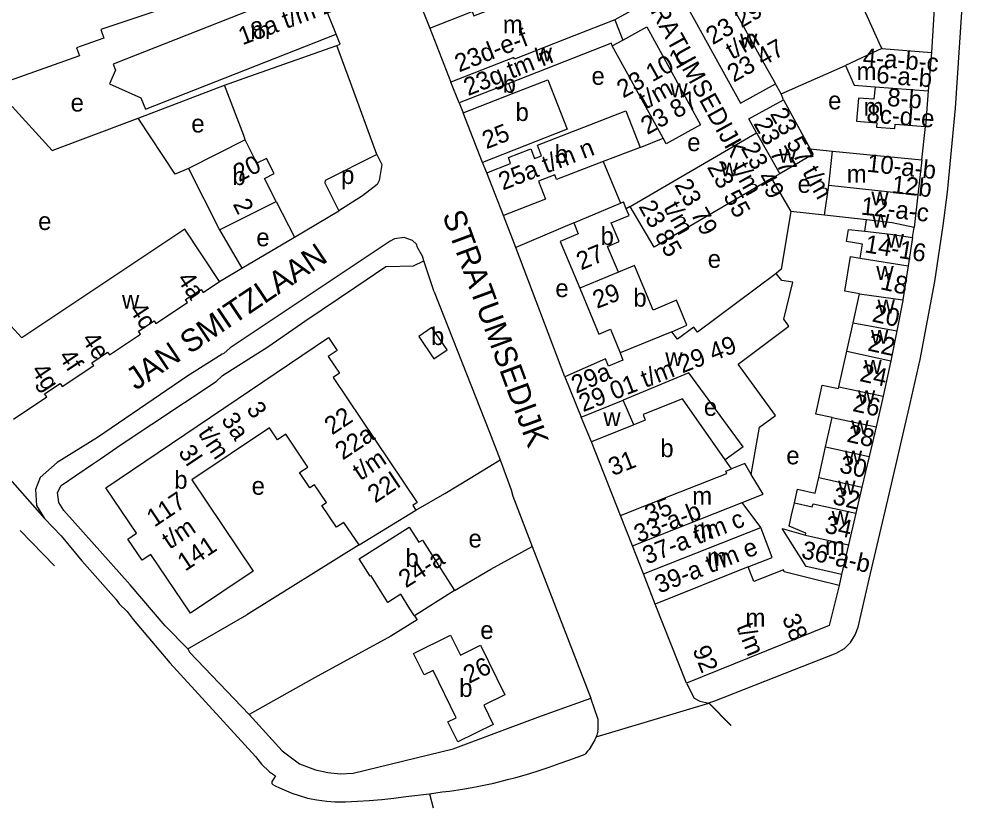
# Model space of a CAD drawing. Extents: x 160673 to 161924, y 382258 to 384145.
# Drawn here: x 161653.4 to 161869.1, y 382580.1 to 382756.1 of the extents above; entities that cross this region are included whole.
import ezdxf

# ---------------------------------------------------------------- set-up
doc = ezdxf.new("R2010")
doc.units = 0
for name, color, linetype in [('BLT_Basislijn', 7, 'Continuous'), ('BLT_Bebouwing', 7, 'Continuous'), ('BLT_Centroide', 7, 'Continuous'), ('BLT_Huisnummer', 7, 'Continuous'), ('BLT_Huisnummer_ tussenligend', 7, 'Continuous'), ('BLT_Huisnummer_reeks', 7, 'Continuous'), ('BLT_Onderdoorgang_en_onderverdeling', 7, 'Continuous'), ('BLT_Onderverdeling_panden', 7, 'Continuous'), ('BLT_Straatnaam', 7, 'Continuous'), ('BLT_Straatnaam_verkleind', 7, 'Continuous'), ('BLT_Vlakafsluiter', 7, 'Continuous')]:
    doc.layers.add(name, color=color, linetype=linetype)

msp = doc.modelspace()

# ---------------------------------------------------------------- linework, layer by layer
at = {"layer": 'BLT_Basislijn'}
for p, q in [((161858.54, 382773.49), (161856.96, 382748.72)), ((161725, 382750.53), (161724.12, 382752.78)), ((161703.58, 382742.99), (161724.28, 382750.28)), ((161724.28, 382750.28), (161725, 382750.53)), ((161727.3, 382742.02), (161724.28, 382750.28)), ((161679.92, 382734.05), (161699.17, 382741.44)), ((161699.17, 382741.44), (161703.58, 382742.99)), ((161733.21, 382725.92), (161727.3, 382742.02)), ((161823.94, 382738.13), (161823.46, 382739.44)), ((161651.83, 382736.65), (161660.76, 382726.8)), ((161660.76, 382726.8), (161678.7, 382733.58)), ((161678.7, 382733.58), (161679.92, 382734.05)), ((161854.84, 382724.77), (161855.64, 382732.18)), ((161791.96, 382727.48), (161797.09, 382729.59)), ((161829.95, 382727.23), (161834.91, 382726.68)), ((161757.72, 382721.84), (161756.79, 382724.17)), ((161783.73, 382724.36), (161787.6, 382715.06)), ((161821.32, 382720.58), (161825.63, 382713.21)), ((161710.71, 382715.47), (161714.79, 382707.51)), ((161714.79, 382707.51), (161724.69, 382713.39)), ((161789.75, 382714.35), (161788.88, 382713.84)), ((161764.23, 382705.15), (161761.43, 382712.3)), ((161698.11, 382709.1), (161703.05, 382700.53)), ((161777.14, 382710.66), (161764.23, 382705.15)), ((161703.05, 382700.53), (161714.79, 382707.51)), ((161775.14, 382676.31), (161764.23, 382705.15)), ((161698.1, 382697.59), (161703.05, 382700.53)), ((161746.02, 382695.31), (161743.67, 382702.18)), ((161717.1, 382688.7), (161728.47, 382696.41)), ((161746.02, 382695.31), (161758.32, 382663.94)), ((161758.32, 382663.94), (161760.69, 382657.74)), ((161671.49, 382658.02), (161673.45, 382659.36)), ((161673.45, 382659.36), (161675.93, 382661.02)), ((161669.7, 382656.79), (161671.49, 382658.02)), ((161653.59, 382641.98), (161661.27, 382634.08)), ((161729.23, 382638.83), (161704.19, 382623.18)), ((161767.86, 382638.41), (161780.96, 382604.55)), ((161836.9, 382632.18), (161836.39, 382629.75)), ((161691.03, 382615.55), (161704.19, 382623.18)), ((161807.26, 382603.48), (161807.31, 382603.5))]:
    msp.add_line(p, q, dxfattribs=at)
for points in [[(161807.31, 382603.5), (161808.62, 382604.01), (161826.42, 382610.98), (161835.69, 382614.61), (161837.55, 382615.63), (161838.9, 382616.97), (161839.97, 382618.7), (161840.6, 382620.41), (161843.11, 382631.15), (161847.83, 382651.39), (161852.26, 382670.37), (161854.47, 382680.15), (161857.74, 382697.6), (161859.63, 382710.05), (161860.56, 382717.51), (161862.36, 382736.25), (161864.15, 382763.42), (161868.36, 382827), (161869.09, 382838.2)], [(161705.29, 382765.14), (161671.57, 382753.82), (161672.26, 382751.88), (161666.99, 382750.02), (161666.19, 382749.74), (161666.83, 382747.94), (161647.7, 382741.2)], [(161703.78, 382729.17), (161703.52, 382730.14), (161699.17, 382741.44)], [(161691.18, 382722.8), (161688.16, 382721.53), (161679.92, 382734.05)], [(161733.21, 382725.92), (161721.67, 382720.16), (161721.6, 382719.59), (161724.69, 382713.39)], [(161733.21, 382725.92), (161734.3, 382723.67), (161733.68, 382720.14), (161733.24, 382719.27), (161729.99, 382716.72), (161724.69, 382713.39)], [(161825.63, 382713.21), (161823.46, 382700.35), (161822.36, 382699.4)], [(161833.12, 382712.37), (161825.63, 382713.21)], [(161743.67, 382702.18), (161743.38, 382703.26), (161742.24, 382705.19), (161742.01, 382705.93), (161741.15, 382706.77), (161739.3, 382707.39), (161737.13, 382707.12), (161736.16, 382706.61), (161700.46, 382682.76), (161699.06, 382681.48), (161698.64, 382681.38), (161690.98, 382676.49), (161670.88, 382662.78), (161661.87, 382657.15), (161658.03, 382653.82), (161657.02, 382651.15), (161657.25, 382647.58), (161659, 382644.71)], [(161728.47, 382696.41), (161735.18, 382700.93), (161741.38, 382701.09), (161743.67, 382702.18)], [(161675.93, 382661.02), (161697.3, 382675.26), (161698.74, 382676.57), (161708.83, 382682.99), (161716.41, 382688.23), (161717.1, 382688.7)], [(161754.05, 382653.68), (161760.69, 382657.74)], [(161760.69, 382657.74), (161763.21, 382651.06), (161763.53, 382649.67), (161767.86, 382638.41)], [(161691.03, 382615.55), (161685.98, 382620.75), (161678.15, 382629.86), (161663.31, 382646.46), (161662.19, 382648.22), (161661.95, 382650.45), (161662.77, 382652.08), (161669.7, 382656.79)], [(161741.88, 382646.56), (161748.39, 382650.23), (161754.05, 382653.68)], [(161659, 382644.71), (161662.77, 382640.82), (161667.34, 382635.24), (161675.02, 382626.6), (161675.65, 382625.64), (161677.43, 382623.92), (161678.77, 382622.1), (161686.99, 382612.44), (161706.14, 382591.55), (161707.48, 382589.83), (161709.23, 382588.1), (161710.6, 382587.23)], [(161750.5, 382628.6), (161758.66, 382633.38), (161767.86, 382638.41)], [(161741.6, 382622.95), (161742.16, 382622.08), (161736.33, 382618.38), (161719.27, 382609.14), (161704.67, 382600.95)], [(161691.03, 382615.55), (161691.41, 382614.82), (161704.67, 382600.95)], [(161802.33, 382607.93), (161804.02, 382604.57), (161805.3, 382603.93), (161807.26, 382603.48)], [(161704.67, 382600.95), (161712.03, 382592.82), (161715.93, 382589.95), (161719.53, 382588.6), (161722.24, 382587.96), (161725.02, 382587.72), (161727.89, 382587.8), (161750.24, 382593.3), (161769.1, 382600.36), (161780.96, 382604.55)], [(161782.52, 382597.2), (161782.62, 382597.64), (161782.57, 382599.81), (161780.96, 382604.55)], [(161782.52, 382597.2), (161782.29, 382596.34), (161782.12, 382595.93)], [(161782.12, 382595.93), (161781.86, 382595.3), (161781.32, 382594.41), (161780.59, 382593.13), (161780.23, 382592.71)], [(161744.97, 382583.21), (161747.8, 382583.63), (161749.4, 382583.79), (161752.35, 382584.23), (161754.47, 382584.62), (161756.71, 382585.06), (161759.33, 382585.62), (161762.38, 382586.39), (161764.2, 382586.85), (161766.57, 382587.53), (161768.96, 382588.26), (161771.66, 382589.15), (161774.15, 382590.03), (161776.04, 382590.74), (161777.91, 382591.4), (161779.7, 382592.06)], [(161710.6, 382587.23), (161709.82, 382586.05), (161709.77, 382585.95), (161709.74, 382585.83), (161709.74, 382585.68), (161709.78, 382585.55), (161709.85, 382585.46), (161709.93, 382585.37), (161710, 382585.33), (161710.53, 382585.04), (161711.5, 382584.56), (161713.02, 382583.86), (161714.2, 382583.4), (161715.87, 382582.82), (161717.71, 382582.28), (161719.79, 382581.86), (161722.03, 382581.57), (161723.85, 382581.45), (161726.19, 382581.45), (161728.89, 382581.55), (161731.51, 382581.7), (161734.34, 382581.94), (161737, 382582.26), (161739.68, 382582.61), (161744.97, 382583.21)]]:
    msp.add_lwpolyline(points, dxfattribs=at)
at = {"layer": 'BLT_Bebouwing'}
for p, q in [((161736.91, 382774.75), (161745, 382754.12)), ((161724.12, 382752.78), (161718.38, 382767.32)), ((161745, 382754.12), (161749.73, 382742.11)), ((161845.9, 382749.6), (161856.96, 382748.72)), ((161856.96, 382748.72), (161856.27, 382740.11)), ((161823.46, 382739.44), (161837.83, 382745.8)), ((161751.57, 382737.48), (161749.73, 382742.11)), ((161763.51, 382739.52), (161762.63, 382741.8)), ((161856.27, 382740.11), (161855.64, 382732.18)), ((161751.57, 382737.48), (161752.44, 382735.22)), ((161756.79, 382724.17), (161752.44, 382735.22)), ((161703.78, 382729.17), (161691.18, 382722.8)), ((161834.1, 382719.12), (161834.91, 382726.68)), ((161834.91, 382726.68), (161854.84, 382724.77)), ((161854.84, 382724.77), (161853.97, 382716.94)), ((161691.18, 382722.8), (161698.11, 382709.1)), ((161761.43, 382712.3), (161757.72, 382721.84)), ((161833.12, 382712.37), (161834.1, 382719.12)), ((161698.11, 382709.1), (161710.71, 382715.47)), ((161787.6, 382715.06), (161788.24, 382715.33)), ((161853.97, 382716.94), (161853.13, 382709.66)), ((161777.14, 382710.66), (161787.6, 382715.06)), ((161842.09, 382708.79), (161842.51, 382711.33)), ((161852.78, 382707.4), (161853.13, 382709.66)), ((161852.78, 382707.4), (161851.81, 382701.05)), ((161851.81, 382701.05), (161850.62, 382693.47)), ((161839.48, 382688.36), (161840.92, 382694.84)), ((161838.08, 382682.05), (161839.48, 382688.36)), ((161849.26, 382686.6), (161847.92, 382679.88)), ((161836.3, 382674.06), (161838.08, 382682.05)), ((161847.92, 382679.88), (161846.18, 382671.98)), ((161775.14, 382676.31), (161778.8, 382667.31)), ((161790.52, 382665.6), (161788.21, 382671.1)), ((161846.18, 382671.98), (161844.66, 382665.15)), ((161781.09, 382661.82), (161778.8, 382667.31)), ((161833.34, 382660.64), (161834.8, 382667.21)), ((161844.66, 382665.15), (161843.1, 382658.54)), ((161787.56, 382645.35), (161781.09, 382661.82)), ((161814.97, 382660.69), (161810.96, 382657.74)), ((161831.82, 382653.84), (161833.34, 382660.64)), ((161843.1, 382658.54), (161841.48, 382651.69)), ((161841.48, 382651.69), (161840.11, 382645.84)), ((161729.23, 382638.83), (161741.88, 382646.56)), ((161790.24, 382638.55), (161787.56, 382645.35)), ((161840.11, 382645.84), (161838.46, 382638.81)), ((161792.7, 382632.3), (161790.24, 382638.55)), ((161838.46, 382638.81), (161836.9, 382632.18)), ((161795.35, 382625.54), (161792.7, 382632.3)), ((161836.39, 382629.75), (161834.17, 382620.78)), ((161802.33, 382607.93), (161795.35, 382625.54))]:
    msp.add_line(p, q, dxfattribs=at)
for points in [[(161782.19, 382767.44), (161786.19, 382769.61), (161792, 382759.11), (161786.31, 382755.99)], [(161718.38, 382767.32), (161708, 382763.22), (161709.29, 382759.89), (161674.33, 382746.06), (161674.84, 382744.75), (161673.54, 382741.71), (161680.53, 382738.61), (161681.59, 382736.05), (161724.12, 382752.78)], [(161839.05, 382764.7), (161845.72, 382749.99), (161845.9, 382749.6)], [(161802.61, 382758.69), (161814.33, 382737.41), (161822.14, 382741.72)], [(161786.31, 382755.99), (161788.07, 382751.49)], [(161788.07, 382751.49), (161793.44, 382754.43), (161805.45, 382732.53), (161797.79, 382728.32), (161797.09, 382729.59)], [(161785.75, 382750.22), (161785.54, 382750.75), (161762.63, 382741.8)], [(161797.09, 382729.59), (161785.75, 382750.22)], [(161837.83, 382745.8), (161839.73, 382741.44), (161844.39, 382741.06)], [(161763.51, 382739.52), (161771.38, 382742.58), (161775.66, 382731.59), (161756.79, 382724.17)], [(161823.46, 382739.44), (161822.14, 382741.72)], [(161844.39, 382741.06), (161844.16, 382738.25), (161840.67, 382738.53), (161840.26, 382733.38), (161844.79, 382733.02), (161844.71, 382732.02), (161848.8, 382731.7), (161848.88, 382732.72), (161855.64, 382732.18)], [(161817.93, 382730.8), (161816.25, 382733.87), (161823.94, 382738.13)], [(161823.94, 382738.13), (161829.95, 382727.23)], [(161757.72, 382721.84), (161763, 382723.89), (161762.56, 382725.24), (161767.22, 382727.05), (161767.57, 382727.19), (161768.4, 382725.05), (161769.98, 382725.67), (161769.08, 382727.98), (161788.77, 382735.66), (161791.96, 382727.48)], [(161789.75, 382714.35), (161817.93, 382730.8)], [(161710.71, 382715.47), (161708.11, 382720.61), (161710.28, 382721.68), (161708.58, 382725.05), (161706.4, 382723.98), (161703.78, 382729.17)], [(161791.96, 382727.48), (161783.73, 382724.36)], [(161829.95, 382727.23), (161830.62, 382726.02), (161823.11, 382721.63)], [(161783.73, 382724.36), (161773.32, 382720.37), (161772.92, 382721.4), (161769.26, 382719.97), (161770.82, 382715.96), (161761.43, 382712.3)], [(161821.32, 382720.58), (161795.07, 382705.25), (161789.75, 382714.35)], [(161823.11, 382721.63), (161821.32, 382720.58)], [(161698.1, 382697.59), (161690.32, 382709.27), (161653.96, 382685.03), (161625.22, 382716.23)], [(161788.88, 382713.84), (161788.24, 382715.33)], [(161787.11, 382699.68), (161784.71, 382705.42), (161787.26, 382706.49), (161785.51, 382710.66), (161789.52, 382712.34), (161788.88, 382713.84)], [(161842.51, 382711.33), (161833.12, 382712.37)], [(161777.14, 382710.66), (161778.15, 382708.23), (161774.1, 382706.53), (161778.49, 382696.07)], [(161841.11, 382702.81), (161841.63, 382705.94), (161838.02, 382706.53), (161838.46, 382709.2), (161842.09, 382708.79)], [(161840.92, 382694.84), (161837.67, 382695.4), (161838.95, 382703.16), (161841.11, 382702.81)], [(161799.04, 382686.38), (161802.42, 382687.8), (161800.07, 382693.4), (161794.87, 382691.22), (161790.69, 382701.18), (161787.11, 382699.68)], [(161822.36, 382699.4), (161804.79, 382686.27), (161803.93, 382687.41), (161800.3, 382684.69), (161799.04, 382686.38)], [(161816.78, 382654.48), (161818.59, 382665.04), (161822.2, 382667.68), (161813.84, 382679.1), (161825.18, 382687.58), (161824, 382689.16), (161826.03, 382697.44), (161823.56, 382697.79), (161822.36, 382699.4)], [(161652.08, 382666.86), (161659.5, 382671.81), (161659.05, 382672.49), (161662.52, 382674.81), (161662.96, 382674.14), (161669.99, 382678.83), (161669.57, 382679.45), (161673.08, 382681.79), (161673.49, 382681.18), (161680.47, 382685.83), (161680.01, 382686.53), (161683.46, 382688.83), (161683.89, 382688.2), (161690.94, 382692.9), (161690.51, 382693.53), (161693.96, 382695.83), (161694.43, 382695.14), (161698.1, 382697.59)], [(161778.49, 382696.07), (161782.77, 382685.84), (161785.36, 382686.93), (161787.48, 382681.63)], [(161850.62, 382693.47), (161850.6, 382693.31), (161849.26, 382686.6)], [(161729.23, 382638.83), (161725.83, 382643.82), (161724.2, 382642.73), (161720.93, 382647.56), (161721.93, 382648.23), (161719.25, 382652.2), (161718.25, 382651.53), (161715.95, 382654.94), (161717.77, 382656.17), (161712.85, 382663.47), (161711.03, 382662.24), (161709.2, 382664.95), (161691.89, 382653.29), (161705.62, 382632.96), (161691.6, 382623.52), (161682.75, 382636.64), (161680.83, 382635.35), (161677.65, 382640.09), (161679.58, 382641.37), (161672.73, 382651.51), (161722.39, 382685.09), (161724.34, 382682.19), (161722.35, 382680.85), (161724.86, 382677.12), (161723.42, 382676.15), (161742.23, 382648.26), (161741.21, 382647.58), (161741.88, 382646.56)], [(161787.48, 382681.63), (161788.12, 382680.02), (161784.93, 382678.68), (161784.25, 382680.3), (161775.14, 382676.31)], [(161814.97, 382660.69), (161802.82, 382677.21), (161788.21, 382671.1)], [(161834.8, 382667.21), (161831.18, 382667.97), (161832.62, 382674.47), (161836.21, 382673.67), (161836.3, 382674.06)], [(161810.96, 382657.74), (161801.41, 382671.4), (161792.61, 382667.88), (161793.11, 382666.63), (161790.52, 382665.6)], [(161814.75, 382648.22), (161819.4, 382650.08), (161816.78, 382654.48)], [(161826.43, 382648.19), (161827.1, 382651.21), (161831.04, 382650.33), (161831.82, 382653.84)], [(161818.92, 382642.64), (161814.75, 382648.22)], [(161828.86, 382640.95), (161828.95, 382641.38), (161825.23, 382642.96), (161825.78, 382645.41), (161826.43, 382648.19)], [(161741.6, 382622.95), (161740.59, 382624.55), (161738.55, 382627.76), (161735.68, 382625.94), (161731.9, 382631.91), (161731.68, 382631.77), (161729.23, 382635.64), (161740.44, 382642.76), (161742.58, 382639.38), (161743.35, 382639.86), (161750.5, 382628.6)], [(161816.04, 382633.87), (161821.46, 382635.99), (161818.92, 382642.64)], [(161836.9, 382632.18), (161832.09, 382633.29), (161829.01, 382633.97), (161828.24, 382635.19), (161823.69, 382642.44), (161828.86, 382640.95)], [(161836.39, 382629.75), (161831.54, 382630.95), (161824.12, 382632.79), (161823.95, 382633.22), (161817.36, 382630.58), (161816.04, 382633.87)], [(161750.5, 382628.6), (161741.6, 382622.95)], [(161834.17, 382620.78), (161802.33, 382607.93)], [(161745.74, 382610.75), (161743.76, 382609.78), (161741.4, 382614.57), (161749.65, 382618.65), (161751.86, 382614.18), (161756.31, 382616.38), (161761.77, 382605.33), (161757.07, 382603.01), (161759.19, 382598.72), (161751.28, 382594.81), (161749.07, 382599.27), (161750.88, 382600.16), (161745.74, 382610.75)], [(161780.23, 382592.71), (161779.7, 382592.06)]]:
    msp.add_lwpolyline(points, dxfattribs=at)
msp.add_lwpolyline([(161742.54, 382685.28), (161745.91, 382680.32), (161748.88, 382682.34), (161745.5, 382687.29)], close=True, dxfattribs=at)
at = {"layer": 'BLT_Onderdoorgang_en_onderverdeling'}
for p, q in [((161762.63, 382741.8), (161751.57, 382737.48)), ((161752.44, 382735.22), (161763.51, 382739.52))]:
    msp.add_line(p, q, dxfattribs=at)
for points in [[(161853.13, 382709.66), (161848.25, 382710.69), (161842.51, 382711.33)], [(161842.09, 382708.79), (161847.88, 382708.15), (161852.78, 382707.4)]]:
    msp.add_lwpolyline(points, dxfattribs=at)
at = {"layer": 'BLT_Onderverdeling_panden'}
for p, q in [((161845.9, 382749.6), (161837.83, 382745.8)), ((161763.78, 382747.61), (161749.73, 382742.11)), ((161844.39, 382741.06), (161856.27, 382740.11)), ((161817.93, 382730.8), (161823.11, 382721.63)), ((161834.1, 382719.12), (161853.97, 382716.94)), ((161841.11, 382702.81), (161851.81, 382701.05)), ((161787.11, 382699.68), (161778.49, 382696.07)), ((161840.92, 382694.84), (161850.62, 382693.47)), ((161839.48, 382688.36), (161849.26, 382686.6)), ((161799.04, 382686.38), (161787.48, 382681.63)), ((161838.08, 382682.05), (161847.92, 382679.88)), ((161836.3, 382674.06), (161846.18, 382671.98)), ((161778.8, 382667.31), (161788.21, 382671.1)), ((161834.8, 382667.21), (161844.66, 382665.15)), ((161790.52, 382665.6), (161781.09, 382661.82)), ((161833.34, 382660.64), (161843.1, 382658.54)), ((161812.36, 382655.74), (161810.96, 382657.74)), ((161831.82, 382653.84), (161841.48, 382651.69)), ((161790.24, 382638.55), (161814.75, 382648.22)), ((161792.7, 382632.3), (161818.92, 382642.64)), ((161828.86, 382640.95), (161838.46, 382638.81)), ((161816.04, 382633.87), (161795.35, 382625.54))]:
    msp.add_line(p, q, dxfattribs=at)
for points in [[(161745, 382754.12), (161754.5, 382757.83), (161754.87, 382756.87), (161772.4, 382763.76)], [(161810.36, 382762.92), (161814.74, 382755.03)], [(161786.31, 382755.99), (161777.19, 382752.42)], [(161814.74, 382755.03), (161818.91, 382747.53)], [(161777.19, 382752.42), (161763.93, 382747.23), (161763.78, 382747.61)], [(161785.75, 382750.22), (161788.07, 382751.49)], [(161818.91, 382747.53), (161822.14, 382741.72)], [(161798.81, 382649.79), (161811.28, 382654.7), (161811.07, 382655.24), (161812.36, 382655.74)], [(161816.78, 382654.48), (161815.33, 382656.93), (161812.36, 382655.74)], [(161787.56, 382645.35), (161798.81, 382649.79)], [(161826.43, 382648.19), (161830.39, 382647.31), (161830.55, 382647.97), (161840.11, 382645.84)]]:
    msp.add_lwpolyline(points, dxfattribs=at)
at = {"layer": 'BLT_Vlakafsluiter'}
for p, q in [((161642.04, 382663.81), (161659, 382644.71)), ((161782.12, 382595.93), (161807.26, 382603.48)), ((161812.22, 382598.45), (161807.26, 382603.48)), ((161812.26, 382598.49), (161807.31, 382603.5)), ((161744.97, 382583.21), (161745.73, 382580.13))]:
    msp.add_line(p, q, dxfattribs=at)

# ---------------------------------------------------------------- texts
at = {"layer": 'BLT_Centroide'}
for s, p in [('m', (161704.94, 382751.69)), ('m', (161761.32, 382752.97)), ('w', (161814.27, 382749.8)), ('w', (161768.41, 382746.72)), ('m', (161840.26, 382742.54)), ('b', (161761.27, 382739.71)), ('e', (161781.11, 382741.49)), ('w', (161798.69, 382738.73)), ('e', (161833.92, 382736.01)), ('e', (161664.84, 382735.52)), ('b', (161764.15, 382733.41)), ('m', (161841.84, 382734.57)), ('e', (161691.78, 382730.85)), ('b', (161772.88, 382724.06)), ('e', (161802.47, 382726.69)), ('w', (161822.94, 382724.1)), ('w', (161809.94, 382721.06)), ('b', (161700.95, 382719.12)), ('p', (161725.21, 382719.35)), ('m', (161838.08, 382719.62)), ('e', (161827.09, 382717.38)), ('w', (161843.57, 382714.56)), ('e', (161657.59, 382709.08)), ('w', (161843.74, 382709.59)), ('b', (161783.14, 382705.73)), ('e', (161706.29, 382705.45)), ('w', (161846.97, 382705.12)), ('e', (161807.05, 382700.64)), ('w', (161844.68, 382697.94)), ('e', (161773.04, 382694.1)), ('b', (161790.45, 382691.97)), ('w', (161676.31, 382691.53)), ('w', (161844.95, 382690.44)), ('b', (161745.27, 382683.39)), ('w', (161843.49, 382683.69)), ('w', (161797.58, 382678.7)), ('w', (161842.02, 382676.97)), ('w', (161840.57, 382670.22)), ('e', (161806.18, 382667.6)), ('w', (161783.75, 382665.3)), ('w', (161839.1, 382663.5)), ('b', (161796.47, 382658.38)), ('e', (161824.58, 382656.77)), ('w', (161837.64, 382656.75)), ('b', (161687.97, 382651.32)), ('e', (161705.24, 382649.98)), ('w', (161836.17, 382650.03)), ('m', (161803.58, 382647.75)), ('w', (161834.71, 382643.28)), ('m', (161803.73, 382640.25)), ('e', (161753.65, 382638.22)), ('b', (161739.59, 382633.86)), ('m', (161833.24, 382636.56)), ('m', (161806.91, 382634.09)), ('m', (161815.48, 382620.56)), ('e', (161756.28, 382617.79)), ('b', (161751.58, 382604.86))]:
    msp.add_text(s, height=4, dxfattribs=at).set_placement(p)
at = {"layer": 'BLT_Huisnummer'}
for s, rotation, p in [('25', 21.287, (161757.65, 382727.08)), ('27', 22.7391, (161778.77, 382700.05)), ('18', 347.4622, (161845.39, 382695.9)), ('29', 21.0034, (161782.31, 382691.46)), ('22', 347.4852, (161842.56, 382682.22)), ('26', 347.4859, (161839.21, 382668.69)), ('31', 21.5143, (161785.85, 382654.12)), ('30', 347.4859, (161836.24, 382655)), ('26', 26.3107, (161753.74, 382607.73))]:
    msp.add_text(s, height=4, rotation=rotation, dxfattribs=at).set_placement(p)
at = {"layer": 'BLT_Huisnummer_ tussenligend'}
for s, rotation, p in [('20', 347.4622, (161843.56, 382688.7)), ('24', 347.4852, (161840.78, 382675.39)), ('28', 347.4859, (161837.9, 382661.86)), ('32', 347.4859, (161834.71, 382647.95)), ('34', 347.4859, (161832.93, 382641.57))]:
    msp.add_text(s, height=4, rotation=rotation, dxfattribs=at).set_placement(p)
at = {"layer": 'BLT_Huisnummer_reeks'}
for s, rotation, p in [('18a t/m z', 20.4703, (161703.19, 382750.3)), ('23 29', 30.549, (161808.16, 382750.3)), ('23d-e-f', 21.3587, (161751.54, 382744.24)), ('t/m', 29.0553, (161812.49, 382747.03)), ('23 47', 29.0628, (161812.83, 382741.95)), ('23g tm n', 21.6296, (161753.55, 382738.95)), ('23 101', 29.0553, (161788.17, 382738.42)), ('4-a-b-c', 355.4215, (161841.54, 382745.75)), ('6-a-b', 355.4215, (161844.54, 382741.91)), ('t/m', 29.0553, (161793.13, 382735.91)), ('23 87', 29.0628, (161793.55, 382730.25)), ('8-b', 355.4335, (161846.98, 382736.79)), ('8c-d-e', 355.4335, (161842.39, 382733.15)), ('23 57 t/m', 299.0588, (161820.86, 382735.04)), ('23 77', 299.0588, (161817.17, 382732.84)), ('25a t/m n', 21.2856, (161761.31, 382717.88)), ('23 49', 299.0588, (161814.4, 382727.35)), ('20', 26.8228, (161702.42, 382719.72)), ('23 55', 299.0588, (161806.81, 382723.13)), ('t/m', 299.0588, (161812.35, 382722.87)), ('10-a-b', 353.7557, (161842.43, 382722.11)), ('23 79', 299.0588, (161799.53, 382719.16)), ('12b', 353.7557, (161847.99, 382717.35)), ('2', 296.8239, (161700.98, 382714.87)), ('23 85', 299.0588, (161791.52, 382714.36)), ('t/m', 299.0588, (161797.07, 382714.1)), ('12-a-c', 353.7557, (161841.11, 382712.55)), ('14-16', 350.6755, (161841.92, 382704.12)), ('4a', 303.6923, (161688.44, 382698.13)), ('4c', 303.6519, (161677.75, 382691.3)), ('4e', 303.6901, (161667.18, 382684.68)), ('29 01 t/m 29 49', 21.3436, (161779.23, 382668.39)), ('4f', 303.6923, (161662.02, 382680.85)), ('4g', 303.6705, (161655.92, 382677.71)), ('29a', 23.0034, (161777.66, 382672.51)), ('3', 303.6923, (161703.95, 382669.12)), ('3a', 303.6923, (161698.33, 382666.72)), ('22', 33.6923, (161723.2, 382663.21)), ('t/m', 303.6923, (161693.14, 382663.69)), ('22a', 33.6923, (161725.59, 382657.6)), ('3l', 303.6923, (161688.73, 382659.48)), ('t/m', 33.6923, (161729.5, 382652.99)), ('22l', 33.6923, (161732.83, 382648)), ('117', 33.6923, (161683.52, 382642.63)), ('35', 21.5147, (161793.97, 382643.65)), ('33-a-b', 21.5143, (161791.57, 382639.22)), ('37-a t/m c', 21.5143, (161793.47, 382634.38)), ('t/m', 33.6923, (161686.93, 382637.69)), ('141', 33.6923, (161690.39, 382632.78)), ('39-a t/m e', 21.8089, (161796.23, 382627.89)), ('36-a-b', 347.4859, (161827.74, 382635.87)), ('24-a', 32.4029, (161739.67, 382629.05)), ('38', 291.8287, (161823.58, 382622.49)), ('t/m', 291.8279, (161813.37, 382620.53)), ('92', 291.8134, (161803.59, 382615.4))]:
    msp.add_text(s, height=4, rotation=rotation, dxfattribs=at).set_placement(p)
at = {"layer": 'BLT_Straatnaam'}
for s, rotation, p in [('STRATUMSEDIJK', 290.246, (161747.75, 382712.44)), ('JAN SMITZLAAN', 33.9765, (161679.41, 382673.17))]:
    msp.add_text(s, height=5, rotation=rotation, dxfattribs=at).set_placement(p)
at = {"layer": 'BLT_Straatnaam_verkleind'}
msp.add_text('STRATUMSEDIJK', height=4, rotation=298.7634, dxfattribs=at).set_placement((161790.87, 382763.99))

doc.saveas('drawing.dxf')
